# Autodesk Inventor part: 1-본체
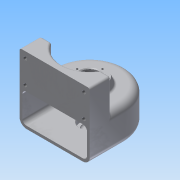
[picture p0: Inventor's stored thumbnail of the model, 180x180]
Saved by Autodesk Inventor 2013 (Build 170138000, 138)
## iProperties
Created: 2015-02
Part Number: 1-본체
Material: 알루미늄 6061
Document SubType Name: Modeling
Designer: Administrator
Density: 2.40731 g/cm^3
Mass: 511.236 g
Surface Area: 706.788 cm^2
Volume: 212.368 cm^3
Author: Administrator
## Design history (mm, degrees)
sketch "스케치1"
  geometry: L1 (-50, 0)-(-50, -50); L2 (-50, -50)-(50, -50); L3 (50, -50)-(50, 0); A1 r 50 centre (0, 0) between (50, 0) and (-50, 0); 1 further point
  constraints: 6 end point, 2 perpendicular, 2 point on circle, 2 tangent, 1 centre point, 1 coincident, 1 horizontal
  dimensions: "d0" = 50 radius of A1; "d2" = 50 distance from line of L2 point (0, 0)
extrude "돌출1" new body sketch "스케치1" distance "d3" = 50; taper "d4" = 0 deg
fillet "모깎기1" dims "d5" = 10
feature "쉘1" dims "d6" = 4
sketch "스케치2"
  geometry: C1 r 25 at (0, 0); A1 r 40 centre (0, 0) between (40, 0) and (-40, 0) reference
  constraints: 1 centre point, 1 coincident
  dimensions: "d7" = 50 diameter of C1
extrude "돌출2" join sketch "스케치2" distance "d9" = 10; taper "d10" = -20 deg
sketch "스케치3"
  geometry: C1 r 20 at (0, 0); A1 r 40 centre (0, 0) between (40, 0) and (-40, 0) reference
  constraints: 1 centre point, 1 coincident
  dimensions: "d11" = 40 diameter of C1
extrude "돌출3" join sketch "스케치3" distance "d13" = 9; taper "d14" = 0 deg
hole "구멍1" diameter "d17" = 20; stored, may be unused: countersink angle "d21" = 90 deg, drill point angle "d23" = 118 deg; dims "d15" = 10, "d16" = 10, "d18" = 6, "d19" = 28, "d20" = 10, "d22" = 8
hole "구멍2" diameter "d26" = 20; stored, may be unused: countersink angle "d30" = 90 deg, drill point angle "d32" = 0 deg; dims "d24" = 10, "d25" = 10, "d27" = 6, "d28" = 28, "d29" = 8, "d31" = 10
node "작업 평면1"
sketch "스케치5"
  geometry: L1 (34.641, -20)-(50, -20); L2 (50, -20)-(50, -50); L3 (50, -50)-(-50, -50); L4 (-50, 0)-(-50, -50) reference; L5 (-50, -50)-(-50, -20); L6 (-34.641, -20)-(-50, -20); L7 (-40, -50)-(40, -50) reference; A1 r 40 centre (0, 0) between (-34.641, -20) and (34.641, -20); 1 further point
  constraints: 10 end point, 2 collinear, 2 perpendicular, 2 point on circle, 2 point on line, 1 centre point, 1 coincident, 1 horizontal, 1 parallel
  dimensions: "d34" = 40 radius of A1; "d36" = 30 distance between parallel lines of L3 L6; "d37" = 100 distance between parallel lines of L4 L2
extrude "돌출4" join sketch "스케치5" stored distance "d38" = 9; taper "d39" = 0 deg
sketch "스케치6"
  geometry: C1 r 14 at (0, 0) reference; C2 r 21.36 at (0, 0) reference; A1 r 18 centre (0, 0) between (0, 18) and (-18, 0); 2 further points
  constraints: 4 point on circle, 2 horizontal alignment, 2 vertical alignment, 1 centre point, 1 coincident
  dimensions: "d40" = 36 diameter of A1
hole "구멍3" sketch "스케치6" at (0, 18), (-18, 0), (0, -18), (18, 0) diameter "d42" = 2.459; stored, may be unused: countersink angle "d46" = 90 deg, drill point angle "d48" = 118 deg; dims "d43" = 6, "d44" = 28, "d45" = 8, "d47" = 9
sketch "스케치8"
  geometry: L1 (-10, 95)-(90, 95) reference; L2 (81.75, 86)-(-1.75, 86); L3 (-1.75, 86)-(-1.75, 53); L4 (-1.75, 53)-(81.75, 53); L5 (81.75, 53)-(81.75, 86); 7 further points
  constraints: 8 end point, 4 coincident, 2 midpoint, 2 parallel, 1 horizontal, 1 perpendicular, 1 vertical alignment
  dimensions: "d49" = 83.5 distance of L2.start L2.end; "d51" = 33 distance of L4.end L2.start; "d52" = 9 distance between parallel lines of L1 L2
hole "구멍4" sketch "스케치8" at (81.75, 86), (81.75, 53), (-1.75, 53), (-1.75, 86) diameter "d53" = 5.134; stored, may be unused: countersink angle "d57" = 90 deg, drill point angle "d59" = 118 deg; dims "d54" = 10, "d55" = 28, "d56" = 8, "d58" = 13
node "작업 평면2"
sketch "스케치9"
  geometry: L1 (-40, 50)-(40, 50) reference; L2 (40, 0)-(-40, 0) reference; 3 further points
  constraints: 1 midpoint, 1 vertical alignment, 1 other
  dimensions: "d60" = 25 distance from line of L2 point (0, 25)
feature "엠보싱1" sketch "스케치9" dims "d0" = 50, "d2" = 50, "d61" = 0.5, "d62" = 0
fillet "모깎기2" dims "d63" = 3
fillet "모깎기3" dims "d64" = 3
fillet "모깎기4" dims "d65" = 3
fillet "모깎기5" dims "d66" = 3
chamfer "모따기1" distance "d67" = 1; stored, may be unused: second distance "d68" = 2, angle "d69" = 45 deg
fillet "모깎기6" dims "d70" = 0.3
node "솔리드1"
other parameters: "d33" = 45
